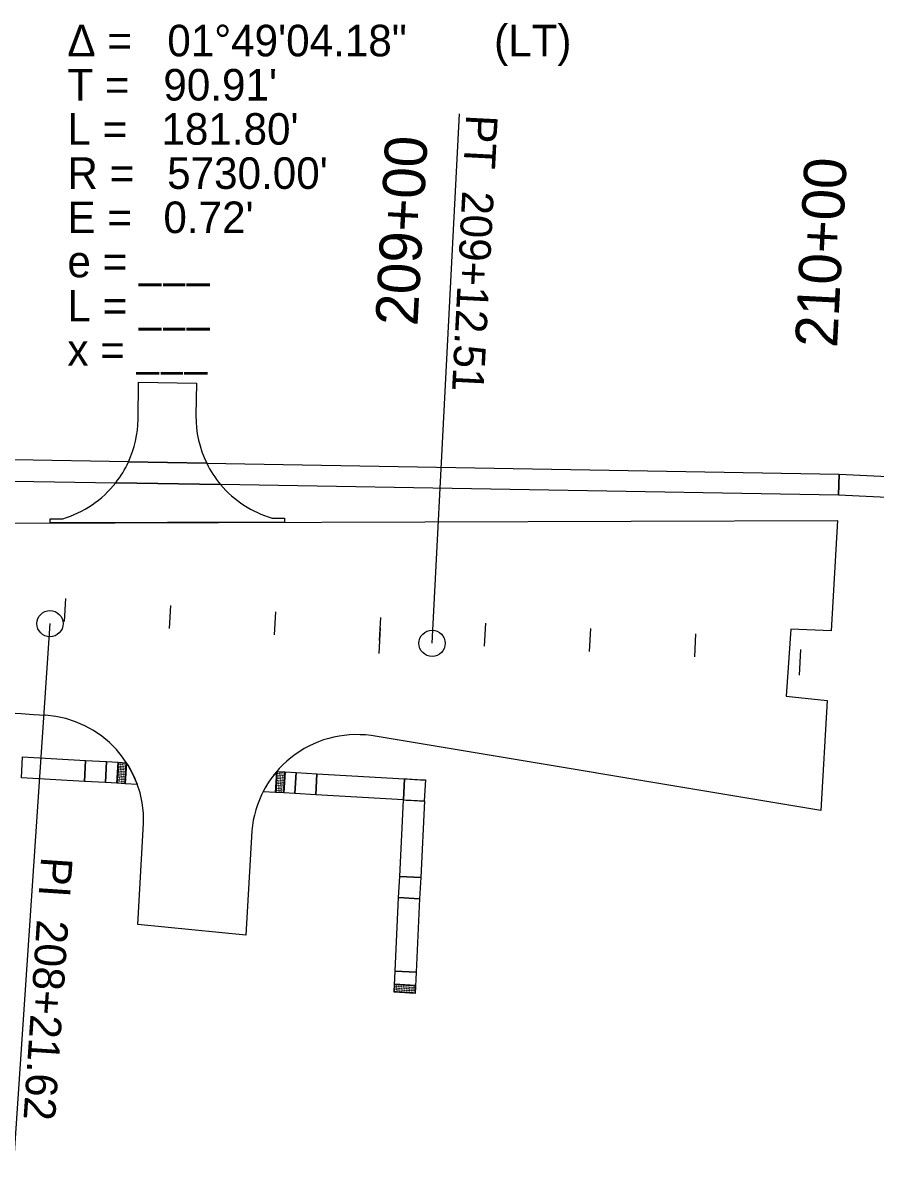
# Model space of a CAD drawing. Extents: x 20499216 to 20505321, y 7953487 to 7960535.
# Drawn here: x 20504513.8 to 20504716.4, y 7953528.2 to 7953802.6 of the extents above; entities that cross this region are included whole.
import ezdxf

# ---------------------------------------------------------------- set-up
doc = ezdxf.new("R2010")
doc.units = 0
for name, color, linetype in [('Drainage', 7, 'Continuous'), ('EXT_CU', 7, 'Continuous'), ('EXT_RR', 7, 'Continuous'), ('NamedBoundary', 7, 'Continuous'), ('Natural', 7, 'Continuous'), ('Roadways', 7, 'Continuous'), ('Safety', 7, 'Continuous')]:
    doc.layers.add(name, color=color, linetype=linetype)

msp = doc.modelspace()

# ---------------------------------------------------------------- linework, layer by layer
at = {"layer": 'Drainage'}
for points in [[(20504513.39, 7953623.25), (20504513.68, 7953628.24), (20504528.65, 7953627.38), (20504528.36, 7953622.39)], [(20504533.36, 7953622.1), (20504533.64, 7953627.09), (20504536.38, 7953626.93), (20504536.09, 7953621.94)], [(20504573.79, 7953619.77), (20504574.08, 7953624.76), (20504576.08, 7953624.65), (20504575.79, 7953619.65)], [(20504575.79, 7953619.65), (20504576.08, 7953624.65), (20504578.65, 7953624.5), (20504578.36, 7953619.51), (20504575.79, 7953619.65)], [(20504608.27, 7953599.51), (20504603.28, 7953599.75), (20504604.16, 7953617.99), (20504609.16, 7953617.75)], [(20504607.18, 7953577.03), (20504602.18, 7953577.28), (20504603.03, 7953594.76), (20504608.03, 7953594.51)]]:
    msp.add_lwpolyline(points, close=True, dxfattribs=at)
for points in [[(20504574.08, 7953624.76), (20504573.79, 7953619.77), (20504570.84, 7953619.94)], [(20504604.41, 7953622.98), (20504604.16, 7953618.02), (20504583.35, 7953619.22), (20504583.63, 7953624.21), (20504604.45, 7953623.01), (20504604.45, 7953622.98)]]:
    msp.add_lwpolyline(points, dxfattribs=at)
for centre, radius, start, end in [((20504593.08, 7953608.49), 25.01, 139.7195, 146.1849), ((20504592.62, 7953608.87), 24.42, 139.4061, 139.7195), ((20504591.67, 7953609.31), 23.39, 145.9602, 152.9831), ((20504920.84, 7959587.48), 5972.88, 266.963149, 266.96358)]:
    msp.add_arc(centre, radius, start, end, dxfattribs=at)
at = {"layer": 'EXT_CU'}
for p, q in [((20504538.83, 7953698.3), (20504557.42, 7953697.98)), ((20504560.72, 7953692.92), (20504535.8, 7953693.34)), ((20504536.09, 7953621.94), (20504536.38, 7953626.93)), ((20504536.38, 7953626.93), (20504538.38, 7953626.82)), ((20504538.38, 7953626.82), (20504538.09, 7953621.83)), ((20504573.79, 7953619.77), (20504574.08, 7953624.76)), ((20504574.08, 7953624.76), (20504576.08, 7953624.65)), ((20504576.08, 7953624.65), (20504575.79, 7953619.65)), ((20504538.09, 7953621.83), (20504536.09, 7953621.94)), ((20504575.79, 7953619.65), (20504573.79, 7953619.77)), ((20504601.94, 7953572.28), (20504602.06, 7953574.28)), ((20504606.93, 7953571.99), (20504601.94, 7953572.28)), ((20504602.06, 7953574.28), (20504607.05, 7953573.99)), ((20504607.05, 7953573.99), (20504606.93, 7953571.99))]:
    msp.add_line(p, q, dxfattribs=at)
for points in [[(20504538.83, 7953698.3), (20504511.66, 7953698.76), (20504511.5, 7953693.76), (20504535.8, 7953693.34)], [(20504557.42, 7953697.98), (20504707.7, 7953695.4), (20504707.53, 7953690.4), (20504560.72, 7953692.92)], [(20504540.95, 7953621.66), (20504538.09, 7953621.83), (20504538.38, 7953626.82)]]:
    msp.add_lwpolyline(points, dxfattribs=at)
for points in [[(20505028.88, 7953679.93), (20505028.64, 7953674.94), (20504707.53, 7953690.4), (20504707.7, 7953695.4)], [(20504536.09, 7953621.94), (20504536.38, 7953626.93), (20504538.38, 7953626.82), (20504538.09, 7953621.83)]]:
    msp.add_lwpolyline(points, close=True, dxfattribs=at)
for centre, radius in [((20504536.6, 7953626.78), 0.0375), ((20504536.6, 7953626.78), 0.0188), ((20504536.99, 7953626.76), 0.0375), ((20504536.99, 7953626.76), 0.0188), ((20504537.38, 7953626.73), 0.0375), ((20504537.38, 7953626.73), 0.0188), ((20504537.77, 7953626.71), 0.0375), ((20504537.77, 7953626.71), 0.0188), ((20504538.16, 7953626.69), 0.0375), ((20504538.16, 7953626.69), 0.0188), ((20504536.44, 7953624.04), 0.0375), ((20504536.46, 7953624.43), 0.0375), ((20504536.44, 7953624.04), 0.0188), ((20504536.48, 7953624.82), 0.0375), ((20504536.46, 7953624.43), 0.0188), ((20504536.48, 7953624.82), 0.0188), ((20504536.5, 7953625.22), 0.0375), ((20504536.53, 7953625.61), 0.0375), ((20504536.5, 7953625.22), 0.0188), ((20504536.55, 7953626), 0.0375), ((20504536.53, 7953625.61), 0.0188), ((20504536.55, 7953626), 0.0188), ((20504536.57, 7953626.39), 0.0375), ((20504536.57, 7953626.39), 0.0188), ((20504536.83, 7953624.02), 0.0375), ((20504536.85, 7953624.41), 0.0375), ((20504536.83, 7953624.02), 0.0188), ((20504536.85, 7953624.41), 0.0188), ((20504536.87, 7953624.8), 0.0375), ((20504536.87, 7953624.8), 0.0188), ((20504536.9, 7953625.19), 0.0375), ((20504536.92, 7953625.58), 0.0375), ((20504536.9, 7953625.19), 0.0188), ((20504536.94, 7953625.97), 0.0375), ((20504536.92, 7953625.58), 0.0188), ((20504536.94, 7953625.97), 0.0188), ((20504536.96, 7953626.37), 0.0375), ((20504536.96, 7953626.37), 0.0188), ((20504537.22, 7953624), 0.0375), ((20504537.24, 7953624.39), 0.0375), ((20504537.22, 7953624), 0.0188), ((20504537.24, 7953624.39), 0.0188), ((20504537.26, 7953624.78), 0.0375), ((20504537.29, 7953625.17), 0.0375), ((20504537.26, 7953624.78), 0.0188), ((20504537.31, 7953625.56), 0.0375), ((20504537.29, 7953625.17), 0.0188), ((20504537.33, 7953625.95), 0.0375), ((20504537.31, 7953625.56), 0.0188), ((20504537.33, 7953625.95), 0.0188), ((20504537.35, 7953626.34), 0.0375), ((20504537.35, 7953626.34), 0.0188), ((20504537.61, 7953623.97), 0.0375), ((20504537.61, 7953623.97), 0.0188), ((20504537.63, 7953624.37), 0.0375), ((20504537.63, 7953624.37), 0.0188), ((20504537.66, 7953624.76), 0.0375), ((20504537.68, 7953625.15), 0.0375), ((20504537.66, 7953624.76), 0.0188), ((20504537.7, 7953625.54), 0.0375), ((20504537.68, 7953625.15), 0.0188), ((20504537.7, 7953625.54), 0.0188), ((20504537.72, 7953625.93), 0.0375), ((20504537.72, 7953625.93), 0.0188), ((20504537.75, 7953626.32), 0.0375), ((20504537.75, 7953626.32), 0.0188), ((20504538, 7953623.95), 0.0375), ((20504538, 7953623.95), 0.0188), ((20504538.02, 7953624.34), 0.0375), ((20504538.05, 7953624.73), 0.0375), ((20504538.02, 7953624.34), 0.0188), ((20504538.07, 7953625.13), 0.0375), ((20504538.05, 7953624.73), 0.0188), ((20504538.09, 7953625.52), 0.0375), ((20504538.07, 7953625.13), 0.0188), ((20504538.09, 7953625.52), 0.0188), ((20504538.11, 7953625.91), 0.0375), ((20504538.14, 7953626.3), 0.0375), ((20504538.11, 7953625.91), 0.0188), ((20504538.14, 7953626.3), 0.0188), ((20504574.27, 7953624.22), 0.0375), ((20504574.27, 7953624.22), 0.0187), ((20504574.29, 7953624.61), 0.0375), ((20504574.29, 7953624.61), 0.0187), ((20504574.66, 7953624.19), 0.0375), ((20504574.66, 7953624.19), 0.0187), ((20504574.68, 7953624.58), 0.0375), ((20504574.68, 7953624.58), 0.0187), ((20504575.05, 7953624.17), 0.0375), ((20504575.05, 7953624.17), 0.0187), ((20504575.08, 7953624.56), 0.0375), ((20504575.08, 7953624.56), 0.0187), ((20504575.44, 7953624.15), 0.0375), ((20504575.44, 7953624.15), 0.0187), ((20504575.47, 7953624.54), 0.0375), ((20504575.47, 7953624.54), 0.0187), ((20504575.83, 7953624.13), 0.0375), ((20504575.86, 7953624.52), 0.0375), ((20504575.83, 7953624.13), 0.0187), ((20504575.86, 7953624.52), 0.0187), ((20504536.32, 7953622.07), 0.0375), ((20504536.32, 7953622.07), 0.0188), ((20504536.35, 7953622.46), 0.0375), ((20504536.37, 7953622.85), 0.0375), ((20504536.35, 7953622.46), 0.0188), ((20504536.39, 7953623.26), 0.0375), ((20504536.37, 7953622.85), 0.0188), ((20504536.39, 7953623.26), 0.0188), ((20504536.41, 7953623.65), 0.0375), ((20504536.41, 7953623.65), 0.0188), ((20504536.71, 7953622.04), 0.0375), ((20504536.74, 7953622.44), 0.0375), ((20504536.71, 7953622.04), 0.0188), ((20504536.76, 7953622.83), 0.0375), ((20504536.74, 7953622.44), 0.0188), ((20504536.76, 7953622.83), 0.0188), ((20504536.78, 7953623.24), 0.0375), ((20504536.78, 7953623.24), 0.0188), ((20504536.81, 7953623.63), 0.0375), ((20504536.81, 7953623.63), 0.0188), ((20504537.11, 7953622.02), 0.0375), ((20504537.13, 7953622.41), 0.0375), ((20504537.11, 7953622.02), 0.0188), ((20504537.15, 7953622.8), 0.0375), ((20504537.13, 7953622.41), 0.0188), ((20504537.15, 7953622.8), 0.0188), ((20504537.17, 7953623.22), 0.0375), ((20504537.2, 7953623.61), 0.0375), ((20504537.17, 7953623.22), 0.0188), ((20504537.2, 7953623.61), 0.0188), ((20504537.5, 7953622), 0.0375), ((20504537.52, 7953622.39), 0.0375), ((20504537.5, 7953622), 0.0188), ((20504537.54, 7953622.78), 0.0375), ((20504537.52, 7953622.39), 0.0188), ((20504537.54, 7953622.78), 0.0188), ((20504537.57, 7953623.19), 0.0375), ((20504537.59, 7953623.58), 0.0375), ((20504537.57, 7953623.19), 0.0188), ((20504537.59, 7953623.58), 0.0188), ((20504537.89, 7953621.98), 0.0375), ((20504537.91, 7953622.37), 0.0375), ((20504537.89, 7953621.98), 0.0188), ((20504537.91, 7953622.37), 0.0188), ((20504537.93, 7953622.76), 0.0375), ((20504537.93, 7953622.76), 0.0188), ((20504537.96, 7953623.17), 0.0375), ((20504537.98, 7953623.56), 0.0375), ((20504537.96, 7953623.17), 0.0188), ((20504537.98, 7953623.56), 0.0188), ((20504574.11, 7953621.48), 0.0375), ((20504574.11, 7953621.48), 0.0187), ((20504574.14, 7953621.87), 0.0375), ((20504574.16, 7953622.26), 0.0375), ((20504574.14, 7953621.87), 0.0187), ((20504574.18, 7953622.65), 0.0375), ((20504574.16, 7953622.26), 0.0187), ((20504574.18, 7953622.65), 0.0187), ((20504574.2, 7953623.04), 0.0375), ((20504574.2, 7953623.04), 0.0187), ((20504574.23, 7953623.43), 0.0375), ((20504574.25, 7953623.82), 0.0375), ((20504574.23, 7953623.43), 0.0187), ((20504574.25, 7953623.82), 0.0187), ((20504574.5, 7953621.46), 0.0375), ((20504574.53, 7953621.85), 0.0375), ((20504574.5, 7953621.46), 0.0187), ((20504574.55, 7953622.24), 0.0375), ((20504574.53, 7953621.85), 0.0187), ((20504574.57, 7953622.63), 0.0375), ((20504574.55, 7953622.24), 0.0187), ((20504574.57, 7953622.63), 0.0187), ((20504574.59, 7953623.02), 0.0375), ((20504574.62, 7953623.41), 0.0375), ((20504574.59, 7953623.02), 0.0187), ((20504574.64, 7953623.8), 0.0375), ((20504574.62, 7953623.41), 0.0187), ((20504574.64, 7953623.8), 0.0187), ((20504574.9, 7953621.43), 0.0375), ((20504574.92, 7953621.82), 0.0375), ((20504574.9, 7953621.43), 0.0187), ((20504574.94, 7953622.22), 0.0375), ((20504574.92, 7953621.82), 0.0187), ((20504574.94, 7953622.22), 0.0187), ((20504574.96, 7953622.61), 0.0375), ((20504574.96, 7953622.61), 0.0187), ((20504574.99, 7953623), 0.0375), ((20504575.01, 7953623.39), 0.0375), ((20504574.99, 7953623), 0.0187), ((20504575.03, 7953623.78), 0.0375), ((20504575.01, 7953623.39), 0.0187), ((20504575.03, 7953623.78), 0.0187), ((20504575.29, 7953621.41), 0.0375), ((20504575.31, 7953621.8), 0.0375), ((20504575.29, 7953621.41), 0.0187), ((20504575.33, 7953622.19), 0.0375), ((20504575.31, 7953621.8), 0.0187), ((20504575.33, 7953622.19), 0.0187), ((20504575.35, 7953622.58), 0.0375), ((20504575.35, 7953622.58), 0.0187), ((20504575.38, 7953622.97), 0.0375), ((20504575.4, 7953623.37), 0.0375), ((20504575.38, 7953622.97), 0.0187), ((20504575.42, 7953623.76), 0.0375), ((20504575.4, 7953623.37), 0.0187), ((20504575.42, 7953623.76), 0.0187), ((20504575.68, 7953621.39), 0.0375), ((20504575.7, 7953621.78), 0.0375), ((20504575.68, 7953621.39), 0.0187), ((20504575.72, 7953622.17), 0.0375), ((20504575.7, 7953621.78), 0.0187), ((20504575.72, 7953622.17), 0.0187), ((20504575.74, 7953622.56), 0.0375), ((20504575.77, 7953622.95), 0.0375), ((20504575.74, 7953622.56), 0.0187), ((20504575.79, 7953623.34), 0.0375), ((20504575.77, 7953622.95), 0.0187), ((20504575.81, 7953623.73), 0.0375), ((20504575.79, 7953623.34), 0.0187), ((20504575.81, 7953623.73), 0.0187), ((20504574.02, 7953619.89), 0.0375), ((20504574.02, 7953619.89), 0.0187), ((20504574.04, 7953620.28), 0.0375), ((20504574.07, 7953620.68), 0.0375), ((20504574.04, 7953620.28), 0.0187), ((20504574.09, 7953621.09), 0.0375), ((20504574.07, 7953620.68), 0.0187), ((20504574.09, 7953621.09), 0.0187), ((20504574.41, 7953619.87), 0.0375), ((20504574.41, 7953619.87), 0.0187), ((20504574.44, 7953620.26), 0.0375), ((20504574.46, 7953620.65), 0.0375), ((20504574.44, 7953620.26), 0.0187), ((20504574.48, 7953621.07), 0.0375), ((20504574.46, 7953620.65), 0.0187), ((20504574.48, 7953621.07), 0.0187), ((20504574.8, 7953619.85), 0.0375), ((20504574.8, 7953619.85), 0.0187), ((20504574.83, 7953620.24), 0.0375), ((20504574.85, 7953620.63), 0.0375), ((20504574.83, 7953620.24), 0.0187), ((20504574.87, 7953621.04), 0.0375), ((20504574.85, 7953620.63), 0.0187), ((20504574.87, 7953621.04), 0.0187), ((20504575.19, 7953619.83), 0.0375), ((20504575.22, 7953620.22), 0.0375), ((20504575.19, 7953619.83), 0.0187), ((20504575.24, 7953620.61), 0.0375), ((20504575.22, 7953620.22), 0.0187), ((20504575.24, 7953620.61), 0.0187), ((20504575.26, 7953621.02), 0.0375), ((20504575.26, 7953621.02), 0.0187), ((20504575.59, 7953619.8), 0.0375), ((20504575.61, 7953620.19), 0.0375), ((20504575.59, 7953619.8), 0.0187), ((20504575.63, 7953620.59), 0.0375), ((20504575.61, 7953620.19), 0.0187), ((20504575.63, 7953620.59), 0.0187), ((20504575.65, 7953621), 0.0375), ((20504575.65, 7953621), 0.0187), ((20504602.09, 7953572.5), 0.0375), ((20504602.12, 7953572.89), 0.0375), ((20504602.09, 7953572.5), 0.0188), ((20504602.14, 7953573.28), 0.0375), ((20504602.12, 7953572.89), 0.0188), ((20504602.16, 7953573.67), 0.0375), ((20504602.14, 7953573.28), 0.0188), ((20504602.16, 7953573.67), 0.0188), ((20504602.18, 7953574.06), 0.0375), ((20504602.18, 7953574.06), 0.0188), ((20504602.48, 7953572.47), 0.0375), ((20504602.51, 7953572.86), 0.0375), ((20504602.48, 7953572.47), 0.0188), ((20504602.53, 7953573.26), 0.0375), ((20504602.51, 7953572.86), 0.0188), ((20504602.53, 7953573.26), 0.0188), ((20504602.55, 7953573.65), 0.0375), ((20504602.55, 7953573.65), 0.0188), ((20504602.58, 7953574.04), 0.0375), ((20504602.58, 7953574.04), 0.0188), ((20504602.88, 7953572.45), 0.0375), ((20504602.9, 7953572.84), 0.0375), ((20504602.88, 7953572.45), 0.0188), ((20504602.92, 7953573.23), 0.0375), ((20504602.9, 7953572.84), 0.0188), ((20504602.92, 7953573.23), 0.0188), ((20504602.94, 7953573.62), 0.0375), ((20504602.94, 7953573.62), 0.0188), ((20504602.97, 7953574.02), 0.0375), ((20504602.97, 7953574.02), 0.0188), ((20504603.27, 7953572.43), 0.0375), ((20504603.29, 7953572.82), 0.0375), ((20504603.27, 7953572.43), 0.0188), ((20504603.31, 7953573.21), 0.0375), ((20504603.29, 7953572.82), 0.0188), ((20504603.31, 7953573.21), 0.0188), ((20504603.33, 7953573.6), 0.0375), ((20504603.36, 7953573.99), 0.0375), ((20504603.33, 7953573.6), 0.0188), ((20504603.36, 7953573.99), 0.0188), ((20504603.66, 7953572.41), 0.0375), ((20504603.68, 7953572.8), 0.0375), ((20504603.66, 7953572.41), 0.0188), ((20504603.68, 7953572.8), 0.0188), ((20504603.7, 7953573.19), 0.0375), ((20504603.7, 7953573.19), 0.0188), ((20504603.73, 7953573.58), 0.0375), ((20504603.75, 7953573.97), 0.0375), ((20504603.73, 7953573.58), 0.0188), ((20504603.75, 7953573.97), 0.0188), ((20504604.05, 7953572.38), 0.0375), ((20504604.07, 7953572.77), 0.0375), ((20504604.05, 7953572.38), 0.0188), ((20504604.07, 7953572.77), 0.0188), ((20504604.09, 7953573.17), 0.0375), ((20504604.12, 7953573.56), 0.0375), ((20504604.09, 7953573.17), 0.0188), ((20504604.14, 7953573.95), 0.0375), ((20504604.12, 7953573.56), 0.0188), ((20504604.14, 7953573.95), 0.0188), ((20504604.44, 7953572.36), 0.0375), ((20504604.46, 7953572.75), 0.0375), ((20504604.44, 7953572.36), 0.0188), ((20504604.46, 7953572.75), 0.0188), ((20504604.48, 7953573.14), 0.0375), ((20504604.51, 7953573.53), 0.0375), ((20504604.48, 7953573.14), 0.0188), ((20504604.53, 7953573.92), 0.0375), ((20504604.51, 7953573.53), 0.0188), ((20504604.53, 7953573.92), 0.0188), ((20504604.83, 7953572.34), 0.0375), ((20504604.83, 7953572.34), 0.0188), ((20504604.85, 7953572.73), 0.0375), ((20504604.85, 7953572.73), 0.0188), ((20504604.88, 7953573.12), 0.0375), ((20504604.9, 7953573.51), 0.0375), ((20504604.88, 7953573.12), 0.0188), ((20504604.92, 7953573.9), 0.0375), ((20504604.9, 7953573.51), 0.0188), ((20504604.92, 7953573.9), 0.0188), ((20504605.22, 7953572.32), 0.0375), ((20504605.22, 7953572.32), 0.0188), ((20504605.24, 7953572.71), 0.0375), ((20504605.27, 7953573.1), 0.0375), ((20504605.24, 7953572.71), 0.0188), ((20504605.29, 7953573.49), 0.0375), ((20504605.27, 7953573.1), 0.0188), ((20504605.31, 7953573.88), 0.0375), ((20504605.29, 7953573.49), 0.0188), ((20504605.31, 7953573.88), 0.0188), ((20504605.61, 7953572.29), 0.0375), ((20504605.61, 7953572.29), 0.0188), ((20504605.64, 7953572.68), 0.0375), ((20504605.66, 7953573.08), 0.0375), ((20504605.64, 7953572.68), 0.0188), ((20504605.68, 7953573.47), 0.0375), ((20504605.66, 7953573.08), 0.0188), ((20504605.68, 7953573.47), 0.0188), ((20504605.7, 7953573.86), 0.0375), ((20504605.7, 7953573.86), 0.0188), ((20504606.02, 7953572.27), 0.0375), ((20504606.05, 7953572.66), 0.0375), ((20504606.02, 7953572.27), 0.0188), ((20504606.07, 7953573.05), 0.0375), ((20504606.05, 7953572.66), 0.0188), ((20504606.09, 7953573.44), 0.0375), ((20504606.07, 7953573.05), 0.0188), ((20504606.09, 7953573.44), 0.0188), ((20504606.11, 7953573.83), 0.0375), ((20504606.11, 7953573.83), 0.0188), ((20504606.42, 7953572.25), 0.0375), ((20504606.44, 7953572.64), 0.0375), ((20504606.42, 7953572.25), 0.0188), ((20504606.46, 7953573.03), 0.0375), ((20504606.44, 7953572.64), 0.0188), ((20504606.46, 7953573.03), 0.0188), ((20504606.48, 7953573.42), 0.0375), ((20504606.48, 7953573.42), 0.0188), ((20504606.51, 7953573.81), 0.0375), ((20504606.51, 7953573.81), 0.0188), ((20504606.81, 7953572.22), 0.0375), ((20504606.83, 7953572.62), 0.0375), ((20504606.81, 7953572.22), 0.0188), ((20504606.85, 7953573.01), 0.0375), ((20504606.83, 7953572.62), 0.0188), ((20504606.85, 7953573.01), 0.0188), ((20504606.87, 7953573.4), 0.0375), ((20504606.9, 7953573.79), 0.0375), ((20504606.87, 7953573.4), 0.0188), ((20504606.9, 7953573.79), 0.0188)]:
    msp.add_circle(centre, radius, dxfattribs=at)
for centre, radius, start, end in [((20504516.14, 7953708.78), 25, 321.8835, 335.2149), ((20504516.14, 7953708.78), 25, 321.8835, 335.2149), ((20504579.87, 7953708.99), 25, 206.1291, 219.9981), ((20504579.87, 7953708.99), 25, 206.1291, 219.9981), ((20504516.99, 7953612.92), 25.51, 20.048, 33.022)]:
    msp.add_arc(centre, radius, start, end, dxfattribs=at)
at = {"layer": 'EXT_RR'}
for p, q in [((20504523.62, 7953660.36), (20504523.98, 7953665.81)), ((20504548.56, 7953658.75), (20504548.9, 7953664.19)), ((20504573.52, 7953657.24), (20504573.84, 7953662.69)), ((20504623.45, 7953654.54), (20504623.73, 7953660)), ((20504598.64, 7953658.9), (20504598.32, 7953652.79)), ((20504648.41, 7953653.26), (20504648.69, 7953658.71)), ((20504673.38, 7953651.97), (20504673.66, 7953657.42)), ((20504698.5, 7953653.74), (20504698.19, 7953647.63))]:
    msp.add_line(p, q, dxfattribs=at)
at = {"layer": 'NamedBoundary'}
for p, q in [((20504557.42, 7953697.98), (20504538.83, 7953698.3)), ((20504535.8, 7953693.34), (20504560.72, 7953692.92))]:
    msp.add_line(p, q, dxfattribs=at)
for points in [[(20504541.13, 7953708.44), (20504541.25, 7953717.22), (20504554.97, 7953717.03), (20504554.87, 7953709.32)], [(20504511.17, 7953683.76), (20504707.3, 7953684.41), (20504705.81, 7953658.14), (20504696.22, 7953658.54), (20504695.12, 7953642.6), (20504704.87, 7953641.64), (20504703.39, 7953615.5), (20504596.48, 7953633.27)], [(20504572.95, 7953684.96), (20504575.95, 7953684.97), (20504575.95, 7953683.97), (20504520.22, 7953683.79), (20504520.22, 7953684.79), (20504523.22, 7953684.8)], [(20504568.15, 7953610.62), (20504568.15, 7953610.62), (20504566.72, 7953585.85), (20504541.05, 7953588.36), (20504542.43, 7953612.35), (20504542.43, 7953612.35)]]:
    msp.add_lwpolyline(points, dxfattribs=at)
for centre, radius, start, end in [((20504579.87, 7953708.99), 25, 179.2393, 206.1291), ((20504516.14, 7953708.78), 25, 335.2149, 359.2393), ((20504516.14, 7953708.78), 25, 286.4499, 321.8835), ((20504579.87, 7953708.99), 25, 219.9981, 253.9295), ((20504900.74, 7959314.54), 5689.23, 265.23083, 266.15356), ((20504517.41, 7953613.15), 25.03, 358.1741, 86.1536), ((20504593.08, 7953608.47), 25.03, 82.2088, 175.0656)]:
    msp.add_arc(centre, radius, start, end, dxfattribs=at)
at = {"layer": 'Natural'}
for p, q in [((20504610.98, 7953655.19), (20504617.46, 7953781.02)), ((20504617.46, 7953781.02), (20504617.46, 7953781.02)), ((20504520.19, 7953659.87), (20504511.3, 7953528.17))]:
    msp.add_line(p, q, dxfattribs=at)
for centre in [(20504520.19, 7953659.87), (20504610.98, 7953655.19)]:
    msp.add_circle(centre, 3.12, dxfattribs=at)
at = {"layer": 'Roadways'}
for p, q in [((20504604.16, 7953617.99), (20504604.41, 7953622.98)), ((20504609.41, 7953622.72), (20504609.14, 7953617.73))]:
    msp.add_line(p, q, dxfattribs=at)
for points in [[(20504528.36, 7953622.39), (20504528.65, 7953627.38), (20504533.64, 7953627.09), (20504533.36, 7953622.1)], [(20504578.36, 7953619.51), (20504578.65, 7953624.5), (20504583.63, 7953624.21), (20504583.35, 7953619.22)], [(20504603.03, 7953594.76), (20504603.28, 7953599.75), (20504608.27, 7953599.51), (20504608.03, 7953594.51)], [(20504606.93, 7953571.99), (20504601.94, 7953572.28), (20504602.18, 7953577.28), (20504607.18, 7953577.03)]]:
    msp.add_lwpolyline(points, close=True, dxfattribs=at)
for centre, radius, start, end in [((20504920.84, 7959587.48), 5972.88, 266.963149, 267.011176), ((20504909.83, 7959377.38), 5767.5, 266.962053, 267.011527)]:
    msp.add_arc(centre, radius, start, end, dxfattribs=at)
at = {"layer": 'Safety'}
for p, q in [((20504598.48, 7953655.84), (20504598.77, 7953661.3)), ((20504698.5, 7953653.74), (20504698.19, 7953647.63))]:
    msp.add_line(p, q, dxfattribs=at)

# ---------------------------------------------------------------- texts
at = {"layer": 'EXT_RR'}
for s, rotation, p in [('209+00', 86.9235, (20504607.51, 7953730.47)), ('210+00', 87.0487, (20504707.21, 7953725.32))]:
    msp.add_text(s, height=10.02, rotation=rotation, dxfattribs=at).set_placement(p)
at = {"layer": 'Natural'}
for s, p in [(' (LT)', (20504622.93, 7953794.67)), ('Δ = ', (20504524.33, 7953794.67)), ('01°49\'04.18"', (20504548.07, 7953794.67)), ('T = ', (20504524.33, 7953784.17)), ("90.91'", (20504547.13, 7953784.17)), ('L = ', (20504524.33, 7953773.67)), ("181.80'", (20504546.67, 7953773.67)), ('R = ', (20504524.33, 7953763.17)), ("5730.00'", (20504548.03, 7953763.17)), ('E = ', (20504524.33, 7953752.67)), ("0.72'", (20504547.14, 7953752.67)), ('e = ___ ', (20504524.33, 7953742.17)), ('L = ___', (20504524.33, 7953731.67)), ('x = ___', (20504524.33, 7953721.17))]:
    msp.add_text(s, height=7.5, dxfattribs=at).set_placement(p)
for s, rotation, p in [('PT', 267.0487, (20504619.11, 7953780.93)), ('209+12.51', 267.0487, (20504618.17, 7953762.82)), ('PI ', 266.1397, (20504518.11, 7953604.59)), ('208+21.62', 266.1397, (20504517.1, 7953589.68))]:
    msp.add_text(s, height=7.5, rotation=rotation, dxfattribs=at).set_placement(p)
at = {"layer": 'Safety'}
msp.add_text('210+00', height=10.02, rotation=87.0487, dxfattribs=at).set_placement((20504707.21, 7953725.32))

doc.saveas('drawing.dxf')
